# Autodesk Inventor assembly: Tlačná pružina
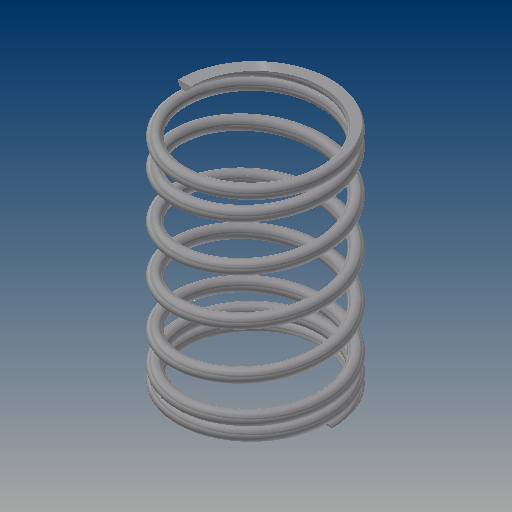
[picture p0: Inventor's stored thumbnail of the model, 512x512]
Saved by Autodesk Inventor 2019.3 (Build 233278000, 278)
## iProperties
ClientObjectVersion: 1
Created: 2019-03
Part Number: Tlačná pružina
Document SubType Name: Assembly
Designer: B-hon
Author: B-hon
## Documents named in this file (2)
- C:\Users\B-hon\OneDrive\Plocha\Bakalářka22\Přítlak\Levý\Přítlak2h\Design Accelerator\Tlačná pružina1.iam
- C:\Users\B-hon\OneDrive\Plocha\Bakalářka22\Přítlak\Levý\Přítlak2h\Design Accelerator\Tlačná pružina11.ipt
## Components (1 placed, 1 different names)
1. Tlačná pružina1:1
